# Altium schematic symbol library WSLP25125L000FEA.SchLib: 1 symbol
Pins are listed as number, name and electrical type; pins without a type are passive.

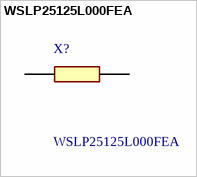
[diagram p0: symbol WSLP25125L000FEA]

## WSLP25125L000FEA
designator X?
Current Sense Resistors - SMD 3watts .005ohms 1%; Manufacturer_Name: Vishay; Geometry.Height: 0.889mm
footprint RESC6432X89N
pins: 1, 2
